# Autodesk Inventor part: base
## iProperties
Author: E. MOSS
Created: 2001-10
Part Number: base
Document SubType Name: Modeling
Designer: E. MOSS
Control State: 0
Master: False
Checked Out: False
PropertySet Name: Design Tracking Control
Shininess: 64.0
Angle Display Precision: 2
Document Length Units: 11272
Document Angle Units: 11286
Document Time Units: 11279
Document Mass Units: 11290
Document Length Units Precision: 3
Document Angle Units Precision: 2
Compacted: False
PropertySet Name: _Private Model Information
Density: 0.0
Volumn: 0.0
Area: 0.0
PropertySet Name: Model Information
